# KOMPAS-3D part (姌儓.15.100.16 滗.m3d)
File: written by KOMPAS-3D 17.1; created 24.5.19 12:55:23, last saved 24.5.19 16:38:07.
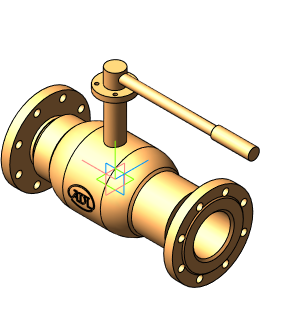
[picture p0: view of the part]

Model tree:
1. Операция без истории:1  (labels: Сталь 20  ГОСТ 1050-2013)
